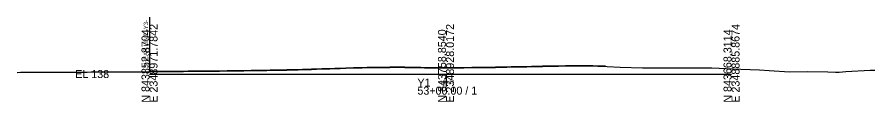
# Model space of a CAD drawing. Extents: x -26 to 2349090, y -10 to 844481.
# Drawn here: x 1000 to 1300, y 18490.3 to 18519.8 of the extents above; entities that cross this region are included whole.
import ezdxf

# ---------------------------------------------------------------- set-up
doc = ezdxf.new("R2010")
doc.units = 0
for name, color, linetype in [('Exist Cross Section Cell', 7, 'Continuous'), ('Exist XS Center Line Elevation Label', 7, 'Continuous'), ('Exist XS Ground Line', 7, 'Continuous'), ('Prop CMT Pvmt Surface', 7, 'Continuous'), ('Prop XS Earthwork Shape', 7, 'Continuous'), ('Prop XS Shear Point Element', 7, 'Continuous'), ('Prop XS Shear Point Label', 7, 'Continuous')]:
    doc.layers.add(name, color=color, linetype=linetype)

msp = doc.modelspace()

# ---------------------------------------------------------------- linework, layer by layer
at = {"layer": 'Exist Cross Section Cell'}
for p, q in [((1046.3, 18500), (1150, 18500)), ((1150, 18500), (1249.87, 18500)), ((1150, 18500), (1150, 18495.6))]:
    msp.add_line(p, q, dxfattribs=at)
at = {"layer": 'Exist XS Ground Line'}
msp.add_lwpolyline([(1000, 18500.59), (1001.16, 18500.6), (1002.22, 18500.62), (1004, 18500.62), (1004.59, 18500.64), (1006.64, 18500.65), (1007.33, 18500.65), (1008.12, 18500.65), (1009.46, 18500.63), (1010.1, 18500.64), (1011.84, 18500.64), (1012.85, 18500.65), (1013.22, 18500.66), (1014.03, 18500.65), (1015.12, 18500.66), (1015.61, 18500.66), (1016.97, 18500.66), (1018.37, 18500.67), (1018.89, 18500.67), (1019.97, 18500.68), (1021.14, 18500.69), (1022.16, 18500.69), (1023.88, 18500.71), (1024.51, 18500.71), (1025.92, 18500.72), (1026.78, 18500.73), (1028.6, 18500.72), (1029.39, 18500.73), (1030.18, 18500.73), (1032.4, 18500.75), (1034.91, 18500.76), (1035.81, 18500.77), (1037.81, 18500.78), (1040.43, 18500.79), (1041.46, 18500.8), (1043.36, 18500.81), (1043.74, 18500.81), (1045.24, 18500.82), (1045.94, 18500.82), (1047.87, 18500.84), (1049, 18500.85), (1049.65, 18500.85), (1050.9, 18500.87), (1051.47, 18500.87), (1052.77, 18500.89), (1054.23, 18500.9), (1054.67, 18500.9), (1055.64, 18500.91), (1056.6, 18500.92), (1057.04, 18500.92), (1058.22, 18500.94), (1059.85, 18500.96), (1061.35, 18500.98), (1062.32, 18500.99), (1063.99, 18501), (1065.2, 18501), (1065.88, 18501.01), (1067.4, 18501.02), (1067.97, 18501.03), (1068.45, 18501.03), (1070.75, 18501.05), (1073.47, 18501.07), (1075.35, 18501.11), (1076.26, 18501.12), (1079.24, 18501.16), (1081.8, 18501.19), (1084.04, 18501.21), (1084.54, 18501.22), (1085.14, 18501.23), (1086.61, 18501.25), (1087.28, 18501.26), (1088.51, 18501.3), (1090.08, 18501.32), (1091.09, 18501.34), (1092.81, 18501.38), (1094.33, 18501.41), (1095.58, 18501.44), (1096.03, 18501.45), (1097, 18501.48), (1097.92, 18501.51), (1098.34, 18501.52), (1099.78, 18501.55), (1101.11, 18501.59), (1101.7, 18501.6), (1102.94, 18501.64), (1103.86, 18501.67), (1104.67, 18501.7), (1106.61, 18501.76), (1107.31, 18501.78), (1108.83, 18501.82), (1109.37, 18501.84), (1111.09, 18501.9), (1112.12, 18501.94), (1112.95, 18501.97), (1114.97, 18502.03), (1117.64, 18502.12), (1120.7, 18502.22), (1122.37, 18502.24), (1123.14, 18502.25), (1125.26, 18502.29), (1125.89, 18502.31), (1126.62, 18502.31), (1128.01, 18502.31), (1128.65, 18502.32), (1130.41, 18502.34), (1131.41, 18502.35), (1132.56, 18502.36), (1134.16, 18502.37), (1135.57, 18502.34), (1136.92, 18502.33), (1137.4, 18502.32), (1138.48, 18502.3), (1139.3, 18502.28), (1139.68, 18502.28), (1141.18, 18502.24), (1142.44, 18502.21), (1144.41, 18502.17), (1145.2, 18502.15), (1146.81, 18502.15), (1147.92, 18502.16), (1150, 18502.17), (1150.33, 18502.17), (1150.71, 18502.17), (1151.04, 18502.17), (1153.46, 18502.18), (1156.29, 18502.2), (1158.98, 18502.23), (1161.34, 18502.26), (1161.92, 18502.27), (1162.26, 18502.27), (1163.77, 18502.28), (1164.5, 18502.29), (1166.54, 18502.33), (1167.26, 18502.34), (1168.06, 18502.36), (1170.01, 18502.41), (1171.28, 18502.45), (1172.79, 18502.48), (1174.06, 18502.5), (1175.07, 18502.52), (1175.55, 18502.52), (1176.83, 18502.54), (1178.28, 18502.56), (1179.94, 18502.59), (1180.68, 18502.61), (1181.02, 18502.61), (1182.59, 18502.66), (1183.8, 18502.69), (1185.93, 18502.72), (1186.58, 18502.73), (1187.17, 18502.74), (1189.34, 18502.79), (1191.74, 18502.83), (1192.05, 18502.83), (1193.87, 18502.84), (1194.81, 18502.84), (1197.72, 18502.85), (1200.34, 18502.84), (1201.38, 18502.83), (1203.08, 18502.8), (1204.09, 18502.79), (1204.63, 18502.77), (1206.32, 18502.65), (1210.92, 18502.45), (1218.77, 18502.11), (1220.68, 18502.13), (1222.99, 18502.12), (1233.1, 18502.2), (1243.02, 18502.14), (1253.1, 18501.65), (1259.7, 18501.42), (1263.05, 18501.23), (1270.13, 18500.76), (1276.3, 18500.84), (1283.5, 18500.75), (1286.29, 18500.71), (1287.47, 18500.71), (1289.8, 18500.88), (1298.37, 18501.34), (1300, 18501.34)], dxfattribs=at)
at = {"layer": 'Prop CMT Pvmt Surface'}
for p, q in [((1050.9, 18500.99), (1051.46, 18501)), ((1051.46, 18501), (1052.77, 18501.01)), ((1052.77, 18501.01), (1054.23, 18501.02)), ((1054.23, 18501.02), (1054.67, 18501.02)), ((1054.67, 18501.02), (1055.64, 18501.03)), ((1055.64, 18501.03), (1056.6, 18501.04)), ((1056.6, 18501.04), (1057.03, 18501.05)), ((1057.03, 18501.05), (1058.22, 18501.06)), ((1058.22, 18501.06), (1059.85, 18501.08)), ((1059.85, 18501.08), (1061.35, 18501.1)), ((1061.35, 18501.1), (1062.32, 18501.11)), ((1062.32, 18501.11), (1063.99, 18501.12)), ((1063.99, 18501.12), (1065.2, 18501.13)), ((1065.2, 18501.13), (1065.88, 18501.13)), ((1065.88, 18501.13), (1067.4, 18501.15)), ((1067.4, 18501.15), (1067.97, 18501.15)), ((1067.97, 18501.15), (1068.45, 18501.15)), ((1068.45, 18501.15), (1070.75, 18501.17)), ((1070.75, 18501.17), (1073.47, 18501.2)), ((1073.47, 18501.2), (1075.34, 18501.23)), ((1075.34, 18501.23), (1076.26, 18501.24)), ((1076.26, 18501.24), (1079.24, 18501.28)), ((1079.24, 18501.28), (1081.8, 18501.31)), ((1081.8, 18501.31), (1084.04, 18501.34)), ((1084.04, 18501.34), (1084.54, 18501.35)), ((1084.54, 18501.35), (1085.13, 18501.35)), ((1085.13, 18501.35), (1086.61, 18501.38)), ((1086.61, 18501.38), (1087.28, 18501.39)), ((1087.28, 18501.39), (1088.51, 18501.42)), ((1088.51, 18501.42), (1090.08, 18501.44)), ((1090.08, 18501.44), (1091.09, 18501.46)), ((1091.09, 18501.46), (1092.81, 18501.5)), ((1092.81, 18501.5), (1094.32, 18501.54)), ((1094.32, 18501.54), (1095.58, 18501.57)), ((1095.58, 18501.57), (1096.03, 18501.57)), ((1096.03, 18501.57), (1097, 18501.6)), ((1097, 18501.6), (1097.92, 18501.63)), ((1097.92, 18501.63), (1098.34, 18501.64)), ((1098.34, 18501.64), (1099.78, 18501.68)), ((1099.78, 18501.68), (1101.11, 18501.71)), ((1101.11, 18501.71), (1101.7, 18501.73)), ((1101.7, 18501.73), (1102.93, 18501.76)), ((1102.93, 18501.76), (1103.85, 18501.79)), ((1103.85, 18501.79), (1104.66, 18501.82)), ((1104.66, 18501.82), (1106.61, 18501.89)), ((1106.61, 18501.89), (1107.31, 18501.91)), ((1107.31, 18501.91), (1108.83, 18501.95)), ((1108.83, 18501.95), (1109.36, 18501.97)), ((1109.36, 18501.97), (1111.09, 18502.03)), ((1111.09, 18502.03), (1112.12, 18502.07)), ((1112.12, 18502.07), (1112.95, 18502.1)), ((1112.95, 18502.1), (1114.96, 18502.16)), ((1114.96, 18502.16), (1117.64, 18502.24)), ((1117.64, 18502.24), (1120.7, 18502.34)), ((1120.7, 18502.34), (1122.37, 18502.37)), ((1122.37, 18502.37), (1123.14, 18502.38)), ((1123.14, 18502.38), (1125.26, 18502.42)), ((1125.26, 18502.42), (1125.89, 18502.43)), ((1125.89, 18502.43), (1126.62, 18502.43)), ((1126.62, 18502.43), (1128.01, 18502.44)), ((1128.01, 18502.44), (1128.65, 18502.44)), ((1128.65, 18502.44), (1130.41, 18502.46)), ((1130.41, 18502.46), (1131.41, 18502.48)), ((1131.41, 18502.48), (1132.56, 18502.49)), ((1132.56, 18502.49), (1134.16, 18502.49)), ((1134.16, 18502.49), (1135.57, 18502.47)), ((1135.57, 18502.47), (1136.92, 18502.45)), ((1136.92, 18502.45), (1137.41, 18502.44)), ((1137.41, 18502.44), (1138.48, 18502.42)), ((1138.48, 18502.42), (1139.31, 18502.41)), ((1139.31, 18502.41), (1139.68, 18502.4)), ((1139.68, 18502.4), (1141.18, 18502.37)), ((1141.18, 18502.37), (1142.44, 18502.33)), ((1142.44, 18502.33), (1144.41, 18502.29)), ((1144.41, 18502.29), (1145.2, 18502.28)), ((1145.2, 18502.28), (1146.81, 18502.28)), ((1146.81, 18502.28), (1147.92, 18502.28)), ((1147.92, 18502.28), (1150, 18502.29)), ((1150, 18502.29), (1150.33, 18502.29)), ((1150.33, 18502.29), (1150.71, 18502.3)), ((1150.71, 18502.3), (1151.04, 18502.3)), ((1151.04, 18502.3), (1153.46, 18502.31)), ((1153.46, 18502.31), (1156.29, 18502.32)), ((1156.29, 18502.32), (1158.98, 18502.35)), ((1158.98, 18502.35), (1161.34, 18502.39)), ((1161.34, 18502.39), (1161.92, 18502.39)), ((1161.92, 18502.39), (1162.26, 18502.39)), ((1162.26, 18502.39), (1163.76, 18502.4)), ((1163.76, 18502.4), (1164.5, 18502.41)), ((1164.5, 18502.41), (1166.54, 18502.45)), ((1166.54, 18502.45), (1167.26, 18502.46)), ((1167.26, 18502.46), (1168.06, 18502.48)), ((1168.06, 18502.48), (1170.01, 18502.54)), ((1170.01, 18502.54), (1171.27, 18502.57)), ((1171.27, 18502.57), (1172.78, 18502.6)), ((1172.78, 18502.6), (1174.06, 18502.62)), ((1174.06, 18502.62), (1175.06, 18502.64)), ((1175.06, 18502.64), (1175.55, 18502.65)), ((1175.55, 18502.65), (1176.83, 18502.67)), ((1176.83, 18502.67), (1178.28, 18502.69)), ((1178.28, 18502.69), (1179.94, 18502.72)), ((1179.94, 18502.72), (1180.67, 18502.73)), ((1180.67, 18502.73), (1181.02, 18502.74)), ((1181.02, 18502.74), (1182.59, 18502.78)), ((1182.59, 18502.78), (1183.79, 18502.82)), ((1183.79, 18502.82), (1185.92, 18502.85)), ((1185.92, 18502.85), (1186.58, 18502.85)), ((1186.58, 18502.85), (1187.16, 18502.87)), ((1187.16, 18502.87), (1189.34, 18502.92)), ((1189.34, 18502.92), (1191.74, 18502.95)), ((1191.74, 18502.95), (1192.05, 18502.96)), ((1192.05, 18502.96), (1193.87, 18502.96)), ((1193.87, 18502.96), (1194.81, 18502.96)), ((1194.81, 18502.96), (1197.72, 18502.97)), ((1197.72, 18502.97), (1200.34, 18502.96)), ((1200.34, 18502.96), (1201.38, 18502.95)), ((1201.38, 18502.95), (1203.08, 18502.92)), ((1203.08, 18502.92), (1204.1, 18502.91)), ((1204.1, 18502.91), (1204.64, 18502.9)), ((1204.64, 18502.9), (1205.64, 18502.83)), ((1205.64, 18502.7), (1205.64, 18502.83)), ((1046.3, 18500.95), (1047.87, 18500.96)), ((1046.3, 18500.83), (1046.3, 18500.95)), ((1047.87, 18500.96), (1049, 18500.97)), ((1049, 18500.97), (1049.65, 18500.98)), ((1049.65, 18500.98), (1050.9, 18500.99))]:
    msp.add_line(p, q, dxfattribs=at)
at = {"layer": 'Prop XS Earthwork Shape'}
msp.add_lwpolyline([(1054.67, 18501.02), (1055.64, 18501.03), (1056.6, 18501.04), (1057.03, 18501.05), (1058.22, 18501.06), (1059.85, 18501.08), (1061.35, 18501.1), (1062.32, 18501.11), (1063.99, 18501.12), (1065.2, 18501.13), (1065.88, 18501.13), (1067.4, 18501.15), (1067.97, 18501.15), (1068.45, 18501.15), (1070.75, 18501.17), (1073.47, 18501.2), (1075.34, 18501.23), (1076.26, 18501.24), (1079.24, 18501.28), (1081.8, 18501.31), (1084.04, 18501.34), (1084.54, 18501.35), (1085.13, 18501.35), (1086.61, 18501.38), (1087.28, 18501.39), (1088.51, 18501.42), (1090.08, 18501.44), (1091.09, 18501.46), (1092.81, 18501.5), (1094.32, 18501.54), (1095.58, 18501.57), (1096.03, 18501.57), (1097, 18501.6), (1097.92, 18501.63), (1098.34, 18501.64), (1099.78, 18501.68), (1101.11, 18501.71), (1101.7, 18501.73), (1102.93, 18501.76), (1103.85, 18501.79), (1104.66, 18501.82), (1106.61, 18501.89), (1107.31, 18501.91), (1108.83, 18501.95), (1109.36, 18501.97), (1111.09, 18502.03), (1112.12, 18502.07), (1112.95, 18502.1), (1114.96, 18502.16), (1117.64, 18502.24), (1120.7, 18502.34), (1122.37, 18502.37), (1123.14, 18502.38), (1125.26, 18502.42), (1125.89, 18502.43), (1126.62, 18502.43), (1128.01, 18502.44), (1128.65, 18502.44), (1130.41, 18502.46), (1131.41, 18502.48), (1132.56, 18502.49), (1134.16, 18502.49), (1135.57, 18502.47), (1136.92, 18502.45), (1137.41, 18502.44), (1138.48, 18502.42), (1139.31, 18502.41), (1139.68, 18502.4), (1141.18, 18502.37), (1142.44, 18502.33), (1144.41, 18502.29), (1145.2, 18502.28), (1146.81, 18502.28), (1147.92, 18502.28), (1150, 18502.29), (1150.33, 18502.29), (1150.71, 18502.3), (1151.04, 18502.3), (1153.46, 18502.31), (1156.29, 18502.32), (1158.98, 18502.35), (1161.34, 18502.39), (1161.92, 18502.39), (1162.26, 18502.39), (1163.76, 18502.4), (1164.5, 18502.41), (1166.54, 18502.45), (1167.26, 18502.46), (1168.06, 18502.48), (1170.01, 18502.54), (1171.27, 18502.57), (1172.78, 18502.6), (1174.06, 18502.62), (1175.06, 18502.64), (1175.55, 18502.65), (1176.83, 18502.67), (1178.28, 18502.69), (1179.94, 18502.72), (1180.67, 18502.73), (1181.02, 18502.74), (1182.59, 18502.78), (1183.79, 18502.82), (1185.92, 18502.85), (1186.58, 18502.85), (1187.16, 18502.87), (1189.34, 18502.92), (1191.74, 18502.95), (1192.05, 18502.96), (1193.87, 18502.96), (1194.81, 18502.96), (1197.72, 18502.97), (1200.34, 18502.96), (1201.38, 18502.95), (1203.08, 18502.92), (1204.1, 18502.91), (1204.64, 18502.9), (1205.64, 18502.83), (1205.64, 18502.7), (1204.63, 18502.77), (1204.09, 18502.79), (1203.08, 18502.8), (1201.38, 18502.83), (1200.34, 18502.84), (1197.72, 18502.85), (1194.81, 18502.84), (1193.87, 18502.84), (1192.05, 18502.83), (1191.74, 18502.83), (1189.34, 18502.79), (1187.17, 18502.74), (1186.58, 18502.73), (1185.93, 18502.72), (1183.8, 18502.69), (1182.59, 18502.66), (1181.02, 18502.61), (1180.68, 18502.61), (1179.94, 18502.59), (1178.28, 18502.56), (1176.83, 18502.54), (1175.55, 18502.52), (1175.07, 18502.52), (1174.06, 18502.5), (1172.79, 18502.48), (1171.28, 18502.45), (1170.01, 18502.41), (1168.06, 18502.36), (1167.26, 18502.34), (1166.54, 18502.33), (1164.5, 18502.29), (1163.77, 18502.28), (1162.26, 18502.27), (1161.92, 18502.27), (1161.34, 18502.26), (1158.98, 18502.23), (1156.29, 18502.2), (1153.46, 18502.18), (1151.04, 18502.17), (1150.71, 18502.17), (1150.33, 18502.17), (1150, 18502.17), (1147.92, 18502.16), (1146.81, 18502.15), (1145.2, 18502.15), (1144.41, 18502.17), (1142.44, 18502.21), (1141.18, 18502.24), (1139.68, 18502.28), (1139.3, 18502.28), (1138.48, 18502.3), (1137.4, 18502.32), (1136.92, 18502.33), (1135.57, 18502.34), (1134.16, 18502.37), (1132.56, 18502.36), (1131.41, 18502.35), (1130.41, 18502.34), (1128.65, 18502.32), (1128.01, 18502.31), (1126.62, 18502.31), (1125.89, 18502.31), (1125.26, 18502.29), (1123.14, 18502.25), (1122.37, 18502.24), (1120.7, 18502.22), (1117.64, 18502.12), (1114.97, 18502.03), (1112.95, 18501.97), (1112.12, 18501.94), (1111.09, 18501.9), (1109.37, 18501.84), (1108.83, 18501.82), (1107.31, 18501.78), (1106.61, 18501.76), (1104.67, 18501.7), (1103.86, 18501.67), (1102.94, 18501.64), (1101.7, 18501.6), (1101.11, 18501.59), (1099.78, 18501.55), (1098.34, 18501.52), (1097.92, 18501.51), (1097, 18501.48), (1096.03, 18501.45), (1095.58, 18501.44), (1094.33, 18501.41), (1092.81, 18501.38), (1091.09, 18501.34), (1090.08, 18501.32), (1088.51, 18501.3), (1087.28, 18501.26), (1086.61, 18501.25), (1085.14, 18501.23), (1084.54, 18501.22), (1084.04, 18501.21), (1081.8, 18501.19), (1079.24, 18501.16), (1076.26, 18501.12), (1075.35, 18501.11), (1073.47, 18501.07), (1070.75, 18501.05), (1068.45, 18501.03), (1067.97, 18501.03), (1067.4, 18501.02), (1065.88, 18501.01), (1065.2, 18501), (1063.99, 18501), (1062.32, 18500.99), (1061.35, 18500.98), (1059.85, 18500.96), (1058.22, 18500.94), (1057.04, 18500.92), (1056.6, 18500.92), (1055.64, 18500.91), (1054.67, 18500.9), (1054.23, 18500.9), (1052.77, 18500.89), (1051.47, 18500.87), (1050.9, 18500.87), (1049.65, 18500.85), (1049, 18500.85), (1047.87, 18500.84), (1046.3, 18500.83), (1046.3, 18500.95), (1047.87, 18500.96), (1049, 18500.97), (1049.65, 18500.98), (1050.9, 18500.99), (1051.46, 18501), (1052.77, 18501.01), (1054.23, 18501.02)], close=True, dxfattribs=at)
at = {"layer": 'Prop XS Shear Point Element'}
msp.add_line((1046.3, 18519.84), (1046.3, 18500.83), dxfattribs=at)
msp.add_line((1046.3, 18519.84), (1046.3, 18500.83), dxfattribs=at)
msp.add_line((1046.3, 18519.84), (1046.3, 18500.83), dxfattribs=at)

# ---------------------------------------------------------------- texts
at = {"layer": 'Exist Cross Section Cell'}
for s, p in [('E 2348971.7842', (1049.1, 18490)), ('E 2348928.0172', (1152.8, 18490)), ('E 2348885.8674', (1252.67, 18490)), ('N 843852.8704', (1046.3, 18490)), ('N 843758.8540', (1150, 18490)), ('N 843668.3114', (1249.87, 18490))]:
    msp.add_text(s, height=2.8, rotation=90, dxfattribs=at).set_placement(p)
for s, p in [('EL 138', (1020.3, 18498.6)), ('Y1', (1140, 18495.6)), ('53+00.00 / 1', (1140, 18492.8))]:
    msp.add_text(s, height=2.8, dxfattribs=at).set_placement(p)
at = {"layer": 'Exist XS Center Line Elevation Label'}
msp.add_text('140.17', height=1.2, dxfattribs=at).set_placement((1147.85, 18496.57))
at = {"layer": 'Prop XS Shear Point Label'}
msp.add_text('SHEAR LINE -Y3-', height=1.5, rotation=90, dxfattribs=at).set_placement((1045.76, 18502.06))
msp.add_text('SHEAR LINE -Y3-', height=1.5, rotation=90, dxfattribs=at).set_placement((1045.76, 18502.06))
msp.add_text('SHEAR LINE -Y3-', height=1.5, rotation=90, dxfattribs=at).set_placement((1045.76, 18502.06))

doc.saveas('drawing.dxf')
